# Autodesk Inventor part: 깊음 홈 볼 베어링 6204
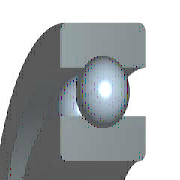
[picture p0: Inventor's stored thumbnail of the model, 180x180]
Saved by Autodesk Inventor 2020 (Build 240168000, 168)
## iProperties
Created: 2012-02
Part Number: 깊음 홈 볼 베어링 6204
Material: 강철, 연강
Description: 깊은 그루부 볼 베어링
Document SubType Name: Modeling
Standard: JIS B 1521
Designer: mdu-01
Standards Organization: JIS
Language: ko-KR
Size Designation: 6204 20x47x14
Categories: <MemberInstance><Categories><Category DisplayName="샤프트 부품" InternalName="7f7aeb1f-a693-4053-b835-cee3144e0d98" Mnemonic="SHFT"><Category DisplayName="베어링" Inter
Density: 1 g/cm^3
Appearance: 강철(1)
IsCustomPart: 1
Author: mdu-01
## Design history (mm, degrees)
sketch "스케치" dims "d0" = 7.02 (= -0.26 x WD + 0.26 x BD)
  geometry: L1 (3.49, 16.75)-(10.51, 16.75); L2 (7, 16.75)-(7, 13.24); L3 (7, 16.75)-(7, 20.26); L4 (4.392, 14.401)-(0, 14.401); L5 (0, 10)-(14, 10); L6 (4.392, 19.099)-(0, 19.099); L7 (0, 23.5)-(14, 23.5); L8 (14, 10)-(14, 14.401); L9 (9.608, 14.401)-(14, 14.401); L10 (9.608, 19.099)-(14, 19.099); L11 (14, 23.5)-(14, 19.099); L12 (-1.4, 0)-(8.4, 0) reference; L13 (0, -0.3)-(0, 5.3) reference
  constraints: 22 end point, 4 point on line, 2 collinear, 2 perpendicular, 2 symmetric about line, 1 midpoint, 1 parallel, 14 other
  dimensions: "d9" = 20 diameter of L5 L12 (= WD); "d11" = 47 diameter of L7 L12 (= BD); "d12" = 14 distance between parallel lines of L8 L13 (= KB); "d13" = 28.802 diameter of L9 L12 (= 0.326 x BD + 0.674 x WD)
revolve "본체" stored, may be unused: angle "d6" = 90 deg
revolve "볼" stored, may be unused: angle "d7" = 90 deg
pattern_circular "IDS_ARRAYBALL[SIMPL:T]" dims angle "d3" = 360 deg
body "Solid1"
fillet "모깎기1" dims "d1" = 1 (= KRS)
other parameters: "WD" = 20 [user parameter; used in 5 equation terms], "BD" = 47 [user parameter; used in 5 equation terms], "KB" = 14 [user parameter; used in 1 equation term], "KRS" = 1 [user parameter; used in 1 equation term], "d4" = 0, "d5" = 0, "d8" = 0, "d14" = 0, "d15" = 0, "BBA" = 0 [user parameter], "BC0" = 6550000 [user parameter], "BC" = 1.27e+07 [user parameter], "BR" = 23.5 (= 0.5 x BD) [user parameter]
